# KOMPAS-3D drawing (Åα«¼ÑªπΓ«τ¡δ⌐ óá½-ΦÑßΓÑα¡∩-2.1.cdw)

Views: Вид 1, Вид 2
Referenced files: Промежуточный вал-шестерня.cdw
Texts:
  Промежуточный вал-шестерня
  Беляев Андрей Константинович
  Noncommercial version
  Модуль
  Число зубьев
  Угол наклона зубьев
  Направление линии зуба
  правое
  Исходный контур
  ГОСТ 13755-81
  Коэффициент смещения
  Степень точности
  по ГОСТ 1643-81
  Длина общей нормали
  Допуск на колебание длины
  общей нормали
  F vw
  За оборот
  колеса
  На одном
  зубе
  Допуск на
  колебание
  измерительного
  межосевого
  расстояния
  радиальное
  биение
  зубчатого
  венца
  погреш-
  ность
  профиля
  зуба
  Отклонение
  основного
  шага
  f '' pt
  Контролировать
  при отсутствии
  обкатки с
  измерительной
  шестерней
  Делительный диаметр
  Ra 1,6
  Ra 1,25
  Ra 2,5
  Термообработка зубьев шестерни и посадочных
  мест - закалка с последующим отпуском.
  * Размер для справок.
  Rz 40
  Промежуточный
  вал-шестерня
  Сталь 40ХН ГОСТ 4543-71
Dimensions and other numbers on the sheet: 5; 18; 14 04'11,52"; 0; 9-B; 38,277 -0,07 -0,15; 0,022; 0,056; 0,025; 0,04; 0,014; 92,784; 320; 55; 73; 40; 85; 33; 34; 2 фаски; 2,5; 70; 1,5; 65; 75; 63; 20; 64; 1,6; 1:2; 1; 12,5; 2; 3; 4; 6; 7; 8; 9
